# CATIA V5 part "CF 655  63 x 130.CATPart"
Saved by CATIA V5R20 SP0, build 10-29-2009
Part number: CF 655  63 x 130
Definition: NONE
Nomenclature: CF 655  63 x 130
Source: Unknown
Description: CF 655  63 x 130
Bounding box of the stored display mesh (mm): x -82 to 48, y -46 to 46, z -46 to 46
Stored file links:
  C:\Users\Utente\Desktop\IO LAVORO\3D X SITO CF\X SITO\CF 655\CF 655  63 x 130.CATPart
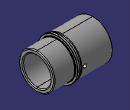
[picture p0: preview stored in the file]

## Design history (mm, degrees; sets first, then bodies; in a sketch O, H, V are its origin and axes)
Body1 "CF 655  63 x 130" (main body)
  Solid1: solid without history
